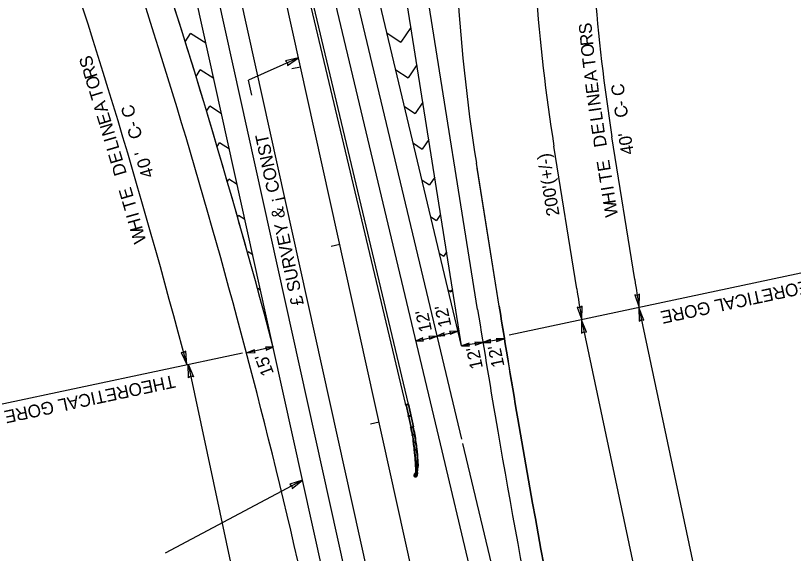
# Model space of a CAD drawing. Extents: x 578088 to 579220, y 1508751 to 1510399.
# Drawn here: x 578418.2 to 578845.7, y 1509092.1 to 1509387.9 of the extents above; entities that cross this region are included whole.
import ezdxf

# ---------------------------------------------------------------- set-up
doc = ezdxf.new("R2010")
doc.units = 0
for name, color, linetype in [('1', 7, 'Continuous'), ('18', 7, 'Continuous'), ('2', 7, 'Continuous'), ('28', 7, 'Continuous'), ('41', 7, 'Continuous'), ('46', 7, 'Continuous'), ('52', 7, 'Continuous'), ('8', 7, 'Continuous')]:
    doc.layers.add(name, color=color, linetype=linetype)

msp = doc.modelspace()

# ---------------------------------------------------------------- linework, layer by layer
at = {"layer": '1'}
for p, q in [((578639.69, 1509066.69), (578362.17, 1510321.74)), ((578559.88, 1509205.29), (578315.3, 1510311.37)), ((578759.9, 1509233.97), (578758.47, 1509234.29)), ((578758.47, 1509234.29), (578760.97, 1509227.35)), ((578761.19, 1509234.74), (578759.9, 1509233.97)), ((578760.97, 1509227.35), (578761.19, 1509234.74)), ((578728.31, 1509227.26), (578726.89, 1509227.58)), ((578726.89, 1509227.58), (578729.39, 1509220.64)), ((578729.61, 1509228.02), (578728.31, 1509227.26)), ((578729.39, 1509220.64), (578729.61, 1509228.02)), ((578760.74, 1509227.31), (578760.88, 1509219.92)), ((578763.57, 1509220.49), (578760.74, 1509227.31)), ((578729.16, 1509220.59), (578729.3, 1509213.21)), ((578731.99, 1509213.78), (578729.16, 1509220.59)), ((578760.88, 1509219.92), (578762.13, 1509220.75)), ((578762.13, 1509220.75), (578763.57, 1509220.49)), ((578729.3, 1509213.21), (578730.55, 1509214.04)), ((578730.55, 1509214.04), (578731.99, 1509213.78))]:
    msp.add_line(p, q, dxfattribs=at)
at = {"layer": '18'}
for p, q in [((578659.48, 1508810.53), (578375.62, 1510094.27)), ((578663.47, 1509155.01), (578558.43, 1509596.29)), ((578663.36, 1509206.35), (578632.08, 1509402.54)), ((578672.16, 1509226.28), (578643.76, 1509404.4)), ((578663.36, 1509206.35), (578617.48, 1509399.06)), ((578635.45, 1509381.4), (578629.99, 1509373.22)), ((578511.53, 1509373.44), (578514.44, 1509378.03)), ((578522.86, 1509372.7), (578514.44, 1509378.03)), ((578622.43, 1509378.26), (578629.99, 1509373.22)), ((578638.73, 1509360.83), (578633.91, 1509353.61)), ((578517.42, 1509354.4), (578519.7, 1509358.01)), ((578527.15, 1509353.3), (578519.7, 1509358.01)), ((578627.24, 1509358.06), (578633.91, 1509353.61)), ((578523.24, 1509335.26), (578524.97, 1509337.99)), ((578531.44, 1509333.9), (578524.97, 1509337.99)), ((578642.01, 1509340.26), (578637.83, 1509334)), ((578632.05, 1509337.86), (578637.83, 1509334)), ((578528.99, 1509315.99), (578530.24, 1509317.97)), ((578535.73, 1509314.49), (578530.24, 1509317.97)), ((578636.86, 1509317.65), (578641.76, 1509314.39)), ((578645.29, 1509319.68), (578641.76, 1509314.39)), ((578684.01, 1509228.17), (578671.91, 1509304.08)), ((578534.66, 1509296.61), (578535.5, 1509297.95)), ((578540.03, 1509295.09), (578535.5, 1509297.95)), ((578641.67, 1509297.45), (578645.68, 1509294.78)), ((578648.57, 1509299.11), (578645.68, 1509294.78)), ((578651.85, 1509278.54), (578649.6, 1509275.17)), ((578540.25, 1509277.1), (578540.77, 1509277.93)), ((578544.32, 1509275.69), (578540.77, 1509277.93)), ((578646.48, 1509277.24), (578649.6, 1509275.17)), ((578545.76, 1509257.47), (578546.04, 1509257.91)), ((578548.61, 1509256.29), (578546.04, 1509257.91)), ((578651.29, 1509257.04), (578653.52, 1509255.55)), ((578655.13, 1509257.96), (578653.52, 1509255.55)), ((578551.2, 1509237.72), (578551.31, 1509237.89)), ((578552.9, 1509236.88), (578551.31, 1509237.89)), ((578656.1, 1509236.83), (578657.44, 1509235.94)), ((578658.41, 1509237.39), (578657.44, 1509235.94)), ((578660.91, 1509216.63), (578661.36, 1509216.33)), ((578661.69, 1509216.82), (578661.36, 1509216.33)), ((578688.9, 1509048.17), (578664.05, 1509152.58))]:
    msp.add_line(p, q, dxfattribs=at)
for centre, radius, start, end in [((579629.37, 1509459.39), 969.97, 176.83826, 189.05927), ((584342.13, 1510130.3), 5729.75, 189.05897, 189.730018), ((584342.13, 1510130.3), 5741.58, 189.05897, 189.735667), ((584342.13, 1510130.3), 5741.58, 189.73613, 192.235242), ((584342.13, 1510130.3), 5729.75, 189.730019, 192.46846)]:
    msp.add_arc(centre, radius, start, end, dxfattribs=at)
at = {"layer": '2'}
for p, q in [((578651.7, 1509152.41), (578547.48, 1509590.23)), ((578656.38, 1509236.37), (578658.33, 1509236.84)), ((578677.17, 1509045.38), (578651.7, 1509152.41))]:
    msp.add_line(p, q, dxfattribs=at)
at = {"layer": '28'}
for p, q in [((578574.92, 1509359.61), (578570.04, 1509358.53)), ((578596.51, 1509261.97), (578591.63, 1509260.89)), ((578618.1, 1509164.33), (578613.22, 1509163.25))]:
    msp.add_line(p, q, dxfattribs=at)
at = {"layer": '41'}
for p, q in [((578671.2, 1508813.02), (578338.64, 1510317)), ((578684.01, 1509228.17), (578671.5, 1509306.66)), ((578684.01, 1509228.17), (578671.5, 1509306.66)), ((578614.13, 1508959.96), (578559.88, 1509205.29))]:
    msp.add_line(p, q, dxfattribs=at)
for centre, radius, start, end in [((574851.28, 1508229.92), 3819.72, 12.46859, 20.71859), ((579629.37, 1509459.39), 969.97, 176.83826, 189.05927), ((579629.37, 1509459.39), 969.97, 176.83826, 189.05927), ((574851.28, 1508229.92), 3834.72, 14.7352, 19.27173), ((584342.13, 1510130.3), 5729.58, 189.05897, 189.729939), ((584342.13, 1510130.3), 5729.58, 189.05897, 189.729939), ((584342.13, 1510130.3), 5729.58, 189.05897, 189.729939), ((584342.13, 1510130.3), 5729.58, 189.72994, 192.46846), ((584342.13, 1510130.3), 5729.58, 189.72994, 192.46846), ((584342.13, 1510130.3), 5729.58, 189.72994, 192.46846)]:
    msp.add_arc(centre, radius, start, end, dxfattribs=at)
at = {"layer": '46'}
for p, q in [((578632.73, 1509173.81), (578580.62, 1509392.73)), ((578634.19, 1509174.14), (578582.08, 1509393.05)), ((578632.56, 1509174.04), (578633.21, 1509174.19)), ((578632.68, 1509173.55), (578632.56, 1509174.04)), ((578633.33, 1509173.7), (578632.68, 1509173.55)), ((578632.73, 1509173.81), (578635.46, 1509161.41)), ((578632.97, 1509173.88), (578635.7, 1509161.47)), ((578633.21, 1509174.19), (578633.86, 1509174.34)), ((578633.21, 1509174.19), (578633.33, 1509173.7)), ((578633.97, 1509173.86), (578633.33, 1509173.7)), ((578633.86, 1509174.34), (578633.97, 1509173.86)), ((578633.92, 1509174.1), (578636.65, 1509161.7)), ((578634.19, 1509174.16), (578636.92, 1509161.76)), ((578633.95, 1509167.86), (578634.6, 1509168.01)), ((578634.06, 1509167.38), (578633.95, 1509167.86)), ((578634.71, 1509167.52), (578634.06, 1509167.38)), ((578634.6, 1509168.01), (578635.25, 1509168.15)), ((578634.6, 1509168.01), (578634.71, 1509167.52)), ((578635.36, 1509167.66), (578634.71, 1509167.52)), ((578635.25, 1509168.15), (578635.36, 1509167.66)), ((578635.29, 1509161.65), (578635.94, 1509161.79)), ((578635.4, 1509161.16), (578635.29, 1509161.65)), ((578636.05, 1509161.31), (578635.4, 1509161.16)), ((578635.94, 1509161.79), (578636.59, 1509161.94)), ((578635.94, 1509161.79), (578636.05, 1509161.31)), ((578636.7, 1509161.45), (578636.05, 1509161.31)), ((578636.59, 1509161.94), (578636.7, 1509161.45)), ((578636.16, 1509157.56), (578636.81, 1509157.68)), ((578636.25, 1509157.07), (578636.16, 1509157.56)), ((578636.9, 1509157.19), (578636.25, 1509157.07)), ((578636.81, 1509157.68), (578637.47, 1509157.8)), ((578636.81, 1509157.68), (578636.9, 1509157.19)), ((578637.56, 1509157.3), (578636.9, 1509157.19)), ((578637.47, 1509157.8), (578637.56, 1509157.3)), ((578636.82, 1509153.43), (578637.48, 1509153.52)), ((578636.88, 1509152.94), (578636.82, 1509153.43)), ((578637.54, 1509153.02), (578636.88, 1509152.94)), ((578637.48, 1509153.52), (578638.14, 1509153.6)), ((578637.48, 1509153.52), (578637.54, 1509153.02)), ((578638.2, 1509153.11), (578637.54, 1509153.02)), ((578638.14, 1509153.6), (578638.2, 1509153.11)), ((578637.3, 1509149.23), (578637.96, 1509149.3)), ((578637.3, 1509149.23), (578637.41, 1509149.24)), ((578637.3, 1509149.22), (578637.3, 1509149.23)), ((578637.35, 1509148.74), (578637.3, 1509149.23)), ((578638.01, 1509148.8), (578637.35, 1509148.74)), ((578637.96, 1509149.3), (578638.62, 1509149.37)), ((578637.96, 1509149.3), (578638.01, 1509148.8)), ((578638.67, 1509148.87), (578638.01, 1509148.8)), ((578638.62, 1509149.37), (578638.67, 1509148.87)), ((578637.91, 1509142.84), (578637.95, 1509142.42)), ((578637.91, 1509142.84), (578637.93, 1509142.84)), ((578639.21, 1509142.96), (578637.93, 1509142.86)), ((578637.93, 1509142.86), (578637.97, 1509142.42)), ((578639.25, 1509142.49), (578637.99, 1509142.39)), ((578637.99, 1509142.38), (578638.62, 1509142.43)), ((578638.22, 1509136.93), (578638.05, 1509142.38)), ((578638.66, 1509138.08), (578638.55, 1509142.43)), ((578638.56, 1509142.91), (578638.6, 1509142.44)), ((578638.56, 1509142.89), (578638.58, 1509142.9)), ((578638.62, 1509142.43), (578638.62, 1509142.44)), ((578638.87, 1509141.42), (578638.88, 1509140.06)), ((578639.42, 1509141.42), (578638.87, 1509141.42)), ((578638.9, 1509141.41), (578638.9, 1509141.45)), ((578638.9, 1509141.45), (578639.15, 1509141.45)), ((578638.93, 1509141.45), (578638.93, 1509141.45)), ((578638.93, 1509141.45), (578639.13, 1509141.45)), ((578638.94, 1509141.53), (578638.94, 1509141.45)), ((578638.97, 1509141.54), (578639.08, 1509141.54)), ((578638.98, 1509141.56), (578638.99, 1509141.57)), ((578638.98, 1509141.56), (578638.98, 1509141.54)), ((578638.99, 1509141.57), (578639.06, 1509141.57)), ((578638.99, 1509141.53), (578638.99, 1509141.45)), ((578639.06, 1509141.57), (578639.07, 1509141.56)), ((578639.06, 1509141.53), (578639.06, 1509141.45)), ((578639.07, 1509141.56), (578639.07, 1509141.54)), ((578639.11, 1509141.53), (578639.11, 1509141.45)), ((578639.13, 1509141.45), (578639.13, 1509141.45)), ((578639.15, 1509141.45), (578639.15, 1509141.42)), ((578639.42, 1509141.41), (578639.43, 1509140.06)), ((578637.91, 1509135.99), (578639.02, 1509137.74)), ((578638.98, 1509140.06), (578638.53, 1509137.28)), ((578639.05, 1509140.06), (578638.61, 1509137.37)), ((578638.66, 1509137.42), (578638.65, 1509137.62)), ((578638.66, 1509137.41), (578638.66, 1509137.43)), ((578638.7, 1509137.45), (578638.68, 1509137.77)), ((578638.76, 1509136.35), (578638.71, 1509137.25)), ((578639.43, 1509140.07), (578638.88, 1509140.06)), ((578638.93, 1509137.86), (578638.94, 1509137.87)), ((578638.93, 1509137.86), (578638.93, 1509137.84)), ((578638.93, 1509137.84), (578638.94, 1509137.83)), ((578638.97, 1509137.87), (578638.94, 1509137.87)), ((578638.94, 1509137.83), (578638.96, 1509137.83)), ((578638.97, 1509137.88), (578638.96, 1509137.81)), ((578638.97, 1509137.82), (578639.02, 1509137.82)), ((578638.97, 1509137.79), (578639.01, 1509137.79)), ((578639.03, 1509137.89), (578638.98, 1509137.9)), ((578638.98, 1509137.87), (578639.02, 1509137.86)), ((578639.03, 1509137.94), (578639.01, 1509137.75)), ((578639.03, 1509137.94), (578639.04, 1509137.94)), ((578637.16, 1509134.96), (578637.2, 1509134.86)), ((578637.19, 1509134.82), (578637.19, 1509134.82)), ((578637.19, 1509134.82), (578637.19, 1509134.82)), ((578637.27, 1509134.65), (578637.26, 1509134.65)), ((578637.3, 1509134.89), (578637.29, 1509134.87)), ((578637.34, 1509134.53), (578637.3, 1509134.64)), ((578638.23, 1509136.93), (578637.33, 1509135.63)), ((578637.89, 1509135.95), (578637.33, 1509135.63)), ((578638.23, 1509136.93), (578637.34, 1509135.62)), ((578637.35, 1509135.64), (578637.89, 1509135.95)), ((578637.36, 1509134.85), (578637.35, 1509134.83)), ((578637.5, 1509134.37), (578637.61, 1509134.34)), ((578637.55, 1509135.26), (578637.54, 1509135.24)), ((578637.61, 1509135.21), (578637.6, 1509135.2)), ((578637.62, 1509134.3), (578637.62, 1509134.31)), ((578637.8, 1509135.62), (578637.79, 1509135.6)), ((578637.79, 1509134.23), (578637.8, 1509134.24)), ((578637.8, 1509136.14), (578637.94, 1509136.36)), ((578637.93, 1509134.21), (578637.83, 1509134.25)), ((578637.86, 1509135.58), (578637.85, 1509135.56)), ((578638, 1509136.31), (578637.86, 1509136.1)), ((578638.19, 1509136.43), (578637.99, 1509136.57)), ((578638.45, 1509135.5), (578638, 1509135.67)), ((578638.1, 1509135.98), (578638.17, 1509136.39)), ((578638.13, 1509135.97), (578638.1, 1509135.98)), ((578638.11, 1509135.89), (578638.19, 1509136.42)), ((578638.74, 1509135.79), (578638.11, 1509135.89)), ((578638.75, 1509135.86), (578638.12, 1509135.96)), ((578638.16, 1509134.21), (578638.26, 1509134.26)), ((578638.16, 1509134.21), (578638.26, 1509134.26)), ((578638.19, 1509136.44), (578638.34, 1509136.41)), ((578638.19, 1509136.42), (578638.82, 1509136.33)), ((578638.21, 1509136.73), (578638.22, 1509136.74)), ((578638.42, 1509136.8), (578638.23, 1509136.93)), ((578638.25, 1509136.43), (578638.24, 1509136.52)), ((578638.25, 1509135.79), (578638.26, 1509135.86)), ((578638.29, 1509136.7), (578638.27, 1509136.68)), ((578638.27, 1509135.78), (578638.4, 1509135.76)), ((578638.29, 1509135.79), (578638.3, 1509135.86)), ((578638.29, 1509135.78), (578638.29, 1509135.74)), ((578638.29, 1509135.74), (578638.29, 1509135.73)), ((578638.29, 1509135.73), (578638.36, 1509135.72)), ((578638.29, 1509134.25), (578638.3, 1509134.24)), ((578638.3, 1509134.24), (578638.29, 1509134.25)), ((578638.35, 1509136.47), (578638.34, 1509136.4)), ((578638.36, 1509134.46), (578638.35, 1509134.44)), ((578638.37, 1509135.72), (578638.36, 1509135.72)), ((578638.37, 1509136.48), (578638.5, 1509136.46)), ((578638.38, 1509135.76), (578638.37, 1509135.72)), ((578638.39, 1509136.46), (578638.38, 1509136.39)), ((578638.38, 1509135.78), (578638.39, 1509135.84)), ((578638.4, 1509136.47), (578638.43, 1509136.71)), ((578638.42, 1509135.77), (578638.43, 1509135.84)), ((578638.42, 1509134.9), (578638.42, 1509134.88)), ((578638.43, 1509136.71), (578638.52, 1509136.69)), ((578638.43, 1509134.45), (578638.43, 1509134.43)), ((578638.46, 1509136.87), (578638.44, 1509136.71)), ((578638.48, 1509136.45), (578638.47, 1509136.38)), ((578638.47, 1509134.32), (578638.47, 1509134.32)), ((578638.48, 1509136.46), (578638.52, 1509136.69)), ((578638.49, 1509135.33), (578638.48, 1509135.31)), ((578638.58, 1509134.39), (578638.48, 1509134.36)), ((578638.5, 1509134.88), (578638.49, 1509134.86)), ((578638.56, 1509137.01), (578638.51, 1509136.69)), ((578638.52, 1509136.44), (578638.51, 1509136.37)), ((578638.51, 1509136.39), (578638.82, 1509136.34)), ((578638.56, 1509135.32), (578638.56, 1509135.3)), ((578638.86, 1509136.61), (578638.72, 1509135.64)), ((578638.72, 1509135.64), (578638.9, 1509135.03)), ((578638.82, 1509136.33), (578638.75, 1509135.86)), ((578638.89, 1509135.97), (578638.85, 1509135.71)), ((578638.86, 1509136.61), (578639.13, 1509136.57)), ((578639.13, 1509136.57), (578638.9, 1509135.01)), ((578639.14, 1509136.58), (578638.91, 1509135.01)), ((578639.14, 1509136.58), (578638.92, 1509136.88)), ((578638.92, 1509136.88), (578638.92, 1509136.87)), ((578639.13, 1509136.57), (578638.92, 1509136.87)), ((578638.92, 1509135.7), (578638.96, 1509135.96)), ((578638.94, 1509136.44), (578638.94, 1509136.42)), ((578639.01, 1509136.41), (578639.02, 1509136.43))]:
    msp.add_line(p, q, dxfattribs=at)
msp.add_circle((578637.92, 1509134.81), 0.25, dxfattribs=at)
for centre, radius, start, end in [((578637.99, 1509142.42), 0.0423, 184.766, 274.766), ((578637.99, 1509142.42), 0.0267, 184.766, 274.766), ((578638.29, 1509142.4), 0.0417, 184.766, 4.766), ((578638.97, 1509141.5), 0.0374, 49.0302, 131.4244), ((578639.03, 1509141.47), 0.0674, 59.8574, 120.5972), ((578639.08, 1509141.5), 0.0374, 49.0302, 131.4244), ((578639, 1509137.84), 0.0335, 128.4484, 219.1028), ((578638.98, 1509137.8), 0.0159, 105.7077, 241.8435), ((578638.98, 1509137.88), 0.0159, 105.7077, 241.8435), ((578638.03, 1509135.08), 0.887, 141.8882, 355.264), ((578638.03, 1509135.09), 0.887, 160.5258, 188.5762), ((578638.03, 1509135.08), 0.877, 141.8882, 355.264), ((578638.03, 1509135.09), 0.887, 197.5339, 209.6185), ((578637.18, 1509134.85), 0.0267, 293.5761, 27.0398), ((578637.27, 1509134.63), 0.0267, 20.1128, 113.5762), ((578637.32, 1509134.85), 0.0383, 145.5762, 325.5762), ((578637.33, 1509134.87), 0.0383, 325.5762, 145.5762), ((578638.03, 1509135.09), 0.887, 218.5762, 233.5762), ((578637.57, 1509135.22), 0.0383, 145.5762, 325.5762), ((578637.58, 1509135.23), 0.0383, 325.5762, 145.5762), ((578637.6, 1509134.31), 0.0267, 338.5762, 72.0399), ((578638.03, 1509135.09), 0.887, 242.5338, 254.6185), ((578637.82, 1509135.58), 0.0383, 145.5762, 325.5762), ((578637.82, 1509136.12), 0.0367, 145.5762, 325.5762), ((578637.83, 1509135.6), 0.0383, 325.5762, 145.5762), ((578637.82, 1509134.23), 0.0267, 65.1124, 158.5762), ((578638.08, 1509135.86), 0.21, 145.5762, 248.5762), ((578638.03, 1509135.09), 0.887, 263.5762, 278.5762), ((578637.97, 1509136.33), 0.0367, 325.5762, 145.5762), ((578638.24, 1509136.7), 0.0383, 145.5759, 325.5759), ((578638.25, 1509136.72), 0.0383, 325.5759, 145.5759), ((578638.27, 1509135.8), 0.021, 189.319, 333.8333), ((578638.27, 1509134.23), 0.0267, 23.5762, 117.0396), ((578638.27, 1509134.23), 0.0267, 23.5762, 117.0399), ((578638.34, 1509135.84), 0.0719, 224.4419, 298.7105), ((578638.03, 1509135.09), 0.887, 287.5339, 299.6185), ((578638.37, 1509136.45), 0.021, 9.319, 153.8333), ((578638.39, 1509134.43), 0.0383, 171.5762, 351.5762), ((578638.39, 1509134.45), 0.0383, 351.5762, 171.5762), ((578638.4, 1509135.78), 0.021, 189.319, 333.8333), ((578638.43, 1509136.39), 0.0719, 44.4419, 118.7105), ((578638.46, 1509134.89), 0.0383, 351.5762, 171.5762), ((578638.46, 1509134.87), 0.0383, 171.5762, 351.5762), ((578638.52, 1509135.69), 0.21, 248.5762, 341.677), ((578638.49, 1509134.33), 0.0267, 110.1128, 203.5762), ((578638.5, 1509136.44), 0.021, 9.319, 153.8333), ((578638.52, 1509135.31), 0.0383, 171.5762, 351.5762), ((578638.52, 1509135.33), 0.0383, 351.5762, 171.5762), ((578638.5, 1509136.39), 0.0417, 351.5761, 64.9368), ((578638.03, 1509135.09), 0.887, 308.5762, 336.6266), ((578638.88, 1509135.7), 0.0367, 171.5762, 351.5762), ((578638.92, 1509135.96), 0.0367, 351.5762, 171.5762), ((578638.98, 1509136.44), 0.0383, 351.5764, 171.5764), ((578638.97, 1509136.42), 0.0383, 171.5764, 351.5764)]:
    msp.add_arc(centre, radius, start, end, dxfattribs=at)
for centre, major_axis, ratio, start_param, end_param in [((578550.81, 1509141.99), (20.86, -87.61), 0.964286, 1.468642, 1.562826), ((578550.78, 1509141.99), (20.93, -87.88), 0.964395, 1.468642, 1.562826), ((578552, 1509142.28), (20.86, -87.61), 0.964286, 1.468642, 1.562826), ((578552, 1509142.28), (20.93, -87.88), 0.964395, 1.468642, 1.562826), ((578510.2, 1509136.87), (31.16, -130.86), 0.948697, 1.440864, 1.468634), ((578513.48, 1509137.5), (30.61, -128.57), 0.943102, 1.439674, 1.468634), ((578511.49, 1509137.29), (31.16, -130.86), 0.948697, 1.439884, 1.468634), ((578514.7, 1509137.78), (30.61, -128.57), 0.943102, 1.439551, 1.468634), ((578510.2, 1509136.87), (31.16, -130.86), 0.948697, 1.393285, 1.440864), ((578513.48, 1509137.5), (30.61, -128.57), 0.943102, 1.39137, 1.439674), ((578511.49, 1509137.29), (31.16, -130.86), 0.948697, 1.393285, 1.439884), ((578514.7, 1509137.78), (30.61, -128.57), 0.943102, 1.39137, 1.439551), ((578610.86, 1509140.41), (27.73, 6.6), 0.937456, 5.89231, 6.141691), ((578611.14, 1509140.37), (27.73, 6.6), 0.937456, 5.89231, 6.141691), ((578642.22, 1509132.05), (0.8, 7.04), 0.813532, 0.727223, 0.900583), ((578642.22, 1509132.05), (0.8, 7.03), 0.813845, 0.726535, 0.900584)]:
    msp.add_ellipse(centre, major_axis=major_axis, ratio=ratio, start_param=start_param, end_param=end_param, dxfattribs=at)
at = {"layer": '52'}
for p, q in [((578573.81, 1509364.63), (578546.33, 1509352.32)), ((578573.81, 1509364.63), (578566.62, 1509362.94)), ((578567.74, 1509360.44), (578573.81, 1509364.63)), ((578566.62, 1509362.94), (578567.69, 1509361.89)), ((578567.69, 1509361.89), (578567.74, 1509360.44)), ((578548.09, 1509344.04), (578546.33, 1509352.32)), ((578758.49, 1509242.76), (578745.97, 1509321.25)), ((578726.61, 1509237.68), (578714.1, 1509316.17)), ((578869.57, 1509250.44), (578689.51, 1509212.17)), ((578760.74, 1509227.31), (578832.01, 1508892)), ((578729.16, 1509220.59), (578791.66, 1508926.54)), ((578649.74, 1509211.7), (578661.2, 1509214.42)), ((578661.2, 1509214.42), (578656.78, 1509214.23)), ((578656.78, 1509214.23), (578657.29, 1509213.49)), ((578657.16, 1509212.63), (578661.2, 1509214.42)), ((578638.02, 1509208.9), (578649.74, 1509211.7)), ((578642.06, 1509210.7), (578638.02, 1509208.91)), ((578641.93, 1509209.84), (578642.06, 1509210.7)), ((578642.44, 1509209.09), (578641.93, 1509209.84)), ((578649.74, 1509211.7), (578645.32, 1509211.51)), ((578645.32, 1509211.51), (578645.83, 1509210.77)), ((578645.7, 1509209.9), (578649.74, 1509211.7)), ((578645.83, 1509210.77), (578645.7, 1509209.9)), ((578653.79, 1509213.49), (578649.74, 1509211.7)), ((578649.74, 1509211.7), (578654.17, 1509211.89)), ((578653.66, 1509212.63), (578653.79, 1509213.49)), ((578654.17, 1509211.89), (578653.66, 1509212.63)), ((578657.29, 1509213.49), (578657.16, 1509212.63)), ((578686.73, 1509210.08), (578675.04, 1509208.22)), ((578686.73, 1509210.08), (578682.3, 1509210.23)), ((578682.3, 1509210.23), (578682.76, 1509209.45)), ((578682.56, 1509208.6), (578686.73, 1509210.08)), ((578560.04, 1509205.69), (578545.41, 1509202.41)), ((578560.04, 1509205.69), (578555.61, 1509205.56)), ((578555.61, 1509205.56), (578556.12, 1509204.81)), ((578555.97, 1509203.95), (578560.04, 1509205.69)), ((578638.02, 1509208.91), (578642.44, 1509209.09)), ((578675.04, 1509208.22), (578663.36, 1509206.35)), ((578667.52, 1509207.84), (578663.36, 1509206.35)), ((578663.36, 1509206.35), (578667.78, 1509206.21)), ((578667.33, 1509206.99), (578667.52, 1509207.84)), ((578667.78, 1509206.21), (578667.33, 1509206.99)), ((578675.04, 1509208.22), (578670.61, 1509208.36)), ((578670.61, 1509208.36), (578671.07, 1509207.58)), ((578670.87, 1509206.73), (578675.04, 1509208.22)), ((578671.07, 1509207.58), (578670.87, 1509206.73)), ((578679.21, 1509209.7), (578675.04, 1509208.22)), ((578675.04, 1509208.22), (578679.47, 1509208.07)), ((578679.01, 1509208.85), (578679.21, 1509209.7)), ((578679.47, 1509208.07), (578679.01, 1509208.85)), ((578682.76, 1509209.45), (578682.56, 1509208.6)), ((578405.02, 1509173.15), (578542.9, 1509202.46)), ((578510.62, 1509202.44), (578509.18, 1509202.63)), ((578509.18, 1509202.63), (578512.32, 1509195.96)), ((578511.84, 1509203.32), (578510.62, 1509202.44)), ((578512.32, 1509195.96), (578511.84, 1509203.32)), ((578549.47, 1509204.15), (578545.41, 1509202.41)), ((578545.41, 1509202.41), (578549.83, 1509202.54)), ((578549.33, 1509203.29), (578549.47, 1509204.15)), ((578549.83, 1509202.54), (578549.33, 1509203.29)), ((578556.12, 1509204.81), (578555.97, 1509203.95)), ((578513.15, 1509196.13), (578592.43, 1508823.18)), ((578513.15, 1509196.13), (578516.03, 1509189.33)), ((578513.34, 1509188.76), (578513.15, 1509196.13)), ((578514.55, 1509189.58), (578513.34, 1509188.76)), ((578516.03, 1509189.33), (578514.55, 1509189.58)), ((578575.99, 1509132.43), (578500.53, 1509092.24)), ((578575.99, 1509132.43), (578568.94, 1509130.26)), ((578568.94, 1509130.26), (578570.08, 1509129.28)), ((578570.08, 1509129.28), (578570.23, 1509127.83)), ((578570.23, 1509127.83), (578575.99, 1509132.43))]:
    msp.add_line(p, q, dxfattribs=at)
for centre, radius, start, end in [((574817.44, 1508227.41), 3819.72, 14.68854, 19.14283), ((579703.85, 1509473.98), 969.97, 184.12715, 189.05927), ((579703.85, 1509473.98), 1002.26, 184.12715, 189.05927), ((584416.6, 1510144.89), 5729.58, 189.05897, 189.21503), ((584416.6, 1510144.89), 5761.86, 189.05897, 189.21503)]:
    msp.add_arc(centre, radius, start, end, dxfattribs=at)
at = {"layer": '8'}
msp.add_arc((574851.28, 1508229.92), 3834.72, 15.5225, 18.32289, dxfattribs=at)

# ---------------------------------------------------------------- texts
at = {"layer": '52'}
for s, rotation, p in [('S', 95.6175, (578735.19, 1509378.03)), ('R', 95.6175, (578735.82, 1509371.6)), ('O', 95.6175, (578736.41, 1509365.57)), ('S', 107.1167, (578461.48, 1509360.57)), ('T', 96.9942, (578737.18, 1509359.62)), ('R', 107.1167, (578463.38, 1509354.4)), ('A', 96.9942, (578738.12, 1509351.98)), ('O', 107.1167, (578465.16, 1509348.61)), ('E', 96.9942, (578738.93, 1509345.32)), ('C', 96.9942, (578753.18, 1509344.13)), ('T', 107.1167, (578466.9, 1509342.95)), ('N', 98.3709, (578739.87, 1509338.73)), ('A', 107.1167, (578469.17, 1509335.6)), ('C', 107.1167, (578484.6, 1509333.06)), ('C', 98.3709, (578754.96, 1509332.29)), ('-', 94.9568, (578754.08, 1509338.27)), ('E', 107.1167, (578471.14, 1509329.19)), ('I', 98.3709, (578740.35, 1509335.45)), ('L', 98.3709, (578741.11, 1509330.26)), ('-', 103.5467, (578486.13, 1509327.38)), ('N', 106.4229, (578473, 1509322.93)), ('C', 106.4229, (578488.1, 1509321.21)), ('E', 98.3709, (578742.17, 1509323.09)), ('I', 106.4229, (578473.94, 1509319.75)), ('£ SURVEY & ¡ CONST', 102, (578576.71, 1509229.26)), ('D', 99.0591, (578743.26, 1509316.08)), ("40'", 99.0591, (578758.09, 1509311.94)), ('L', 106.4229, (578475.42, 1509314.71)), ('E', 106.4229, (578477.47, 1509307.77)), ("'", 106.4229, (578490.63, 1509312.61)), ('0', 106.4229, (578492.8, 1509305.27)), ("200'(+/-)", 99.0591, (578717.2, 1509278.21)), ('E', 99.0591, (578745.37, 1509302.8)), ('D', 106.4229, (578479.46, 1509301)), ('4', 106.4229, (578494.42, 1509299.77)), ('T', 99.0591, (578746.33, 1509296.79)), ('E', 106.4229, (578483.26, 1509288.1)), ('I', 99.0591, (578747.07, 1509292.18)), ('H', 99.0591, (578748.25, 1509284.76)), ('T', 106.4229, (578484.98, 1509282.26)), ('W', 99.0591, (578749.37, 1509277.71)), ('I', 105.7292, (578486.22, 1509277.8)), ('H', 105.7292, (578488.25, 1509270.57)), ('W', 105.7292, (578490.19, 1509263.7)), ('THEORETICAL GORE', 192, (578865.85, 1509245.07)), ("12'", 102, (578657.8, 1509217.28)), ("12'", 102, (578647.14, 1509214.66)), ("12'", 102, (578686.97, 1509195.24)), ("12'", 102, (578675.12, 1509194.29)), ("15'", 110.8713, (578560.32, 1509191.24)), ('THEORETICAL GORE', 192, (578505.14, 1509190.33))]:
    msp.add_text(s, height=7, rotation=rotation, dxfattribs=at).set_placement(p)

doc.saveas('drawing.dxf')
